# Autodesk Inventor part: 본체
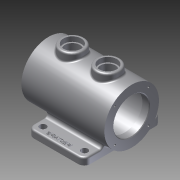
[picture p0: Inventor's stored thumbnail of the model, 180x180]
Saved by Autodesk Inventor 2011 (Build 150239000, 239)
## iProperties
Created: 2014-12
Part Number: 본체
Document SubType Name: Modeling
Designer: user
Density: 1 g/cm^3
Mass: 477.215 g
Surface Area: 1040.06 cm^2
Volume: 477.215 cm^3
Author: user
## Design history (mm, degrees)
sketch "스케치1"
  geometry: L1 (-47.5, 65)-(47.5, 65); L2 (47.5, 65)-(47.5, -65); L3 (47.5, -65)-(-47.5, -65); L4 (-47.5, -65)-(-47.5, 65); 3 further points
  constraints: 8 end point, 2 midpoint, 2 parallel, 1 horizontal, 1 horizontal alignment, 1 perpendicular, 1 vertical alignment
  dimensions: "d0" = 95 distance of L1.start L1.end; "d1" = 130 distance of L1.end L2.end
extrude "돌출1" new body sketch "스케치1" distance "d2" = 12; taper "d3" = 0 deg
sketch "스케치2"
  geometry: L1 (47.5, 12)-(47.5, 0) reference; L2 (47.5, 0)-(-47.5, 0) reference; L3 (-47.5, 0)-(-47.5, 12) reference; L4 (-47.5, 12)-(47.5, 12) reference; L5 (77.5, 50)-(-62.5, 50); L6 (77.5, 80)-(65.5, 80); L7 (65.5, 80)-(65.5, 87.5); L8 (65.5, 87.5)-(-50.5, 87.5); L9 (-50.5, 87.5)-(-50.5, 80); L10 (-50.5, 80)-(-62.5, 80); L11 (-62.5, 80)-(-62.5, 96); L12 (-62.5, 96)-(77.5, 96); L13 (77.5, 96)-(77.5, 80); 3 further points
  constraints: 18 end point, 7 parallel, 2 midpoint, 2 vertical alignment, 1 collinear, 1 perpendicular
  dimensions: "d4" = 50 distance between parallel lines of L2 L5; "d5" = 140 distance of L5.start L5.end; "d6" = 15 horizontal distance of L5.end L2.end; "d7" = 92 diameter of L12 L5; "d8" = 60 diameter of L6 L5; "d9" = 60 diameter of L10 L5; "d10" = 75 diameter of L8 L5; "d11" = 12 distance of L6.start L6.end; "d12" = 12 distance of L9.end L10.end
revolve "회전1" sketch "스케치2" stored, may be unused: angle "d13" = 90 deg
node "작업 평면1"
sketch "스케치3"
  geometry: L1 (62.5, 46)-(62.5, -46) reference; L2 (62.5, 46)-(-77.5, 46) reference; L3 (62.5, -46)-(-77.5, -46) reference; L4 (-77.5, 46)-(-77.5, -46) reference; C1 r 20 at (22.5, 0); C2 r 20 at (-37.5, 0); 2 further points
  constraints: 2 centre point, 2 horizontal alignment, 1 equal radius, 1 midpoint
  dimensions: "d15" = 40 distance from line of L1 C1.centre; "d16" = 40 distance from line of C2.centre L4; "d17" = 40 diameter of C1
extrude "돌출2" join sketch "스케치3" stored distance "d18" = 12; taper "d19" = 0 deg
hole "Hole1" diameter "d22" = 25; stored, may be unused: countersink angle "d26" = 90 deg, drill point angle "d28" = 118 deg; dims "d20" = 10, "d21" = 10, "d23" = 6, "d24" = 30, "d25" = 8, "d27" = 8
hole "Hole2" diameter "d31" = 25; stored, may be unused: countersink angle "d35" = 90 deg, drill point angle "d37" = 118 deg; dims "d29" = 10, "d30" = 10, "d32" = 6, "d33" = 30, "d34" = 8, "d36" = 8
sketch "스케치4" dims "d38" = 80
  geometry: L1 (0, 0)-(28.284, -28.284); L2 (0, 0)-(100.104, 0); C1 r 46 at (0, 0) reference; 1 further point
  constraints: 4 end point, 1 coincident, 1 horizontal, 3 other
  dimensions: "d39" = 45 deg angle of L1 L2
hole "Hole3" sketch "스케치4" at (28.284, -28.284) diameter "d40" = 3.242; stored, may be unused: countersink angle "d44" = 90 deg, drill point angle "d46" = 118 deg; dims "d41" = 8, "d42" = 4, "d43" = 2, "d45" = 10
sketch "스케치5" dims "d50" = 80
  geometry: L1 (0, 0)-(-28.284, 28.284); L2 (0, 0)-(-68.814, 0); C1 r 46 at (0, 0) reference; C2 r 30 at (0, 0) reference; 1 further point
  constraints: 4 end point, 2 coincident, 1 horizontal, 3 other
  dimensions: "d51" = 45 deg angle of L1 L2
hole "Hole4" sketch "스케치5" at (-28.284, 28.284) diameter "d52" = 3.242; stored, may be unused: countersink angle "d56" = 90 deg, drill point angle "d58" = 118 deg; dims "d53" = 8, "d54" = 4, "d55" = 2, "d57" = 10
fillet "모깎기1" dims "d62" = 5
fillet "모깎기2" dims "d63" = 3
chamfer "모따기1" distance "d64" = 1; stored, may be unused: second distance "d65" = 2, angle "d66" = 45 deg
chamfer "모따기2" distance "d67" = 1; stored, may be unused: second distance "d68" = 2, angle "d69" = 45 deg
fillet "모깎기3" dims "d70" = 10
fillet "모깎기4" dims "d71" = 3
fillet "모깎기5" dims "d72" = 3
fillet "모깎기6" dims "d73" = 3
fillet "모깎기7" dims "d74" = 3
sketch "스케치8"
  geometry: L1 (-23.239, -53.998)-(18.239, -53.998); L2 (18.239, -53.998)-(18.239, -60.002); L3 (18.239, -60.002)-(-23.239, -60.002); L4 (-23.239, -60.002)-(-23.239, -53.998); L5 (-23.239, -57)-(18.239, -57); L6 (-2.5, -60.002)-(-2.5, -53.998); L7 (-37.5, -65)-(37.5, -65) reference; C1 r 5.5 at (-37.5, -55) reference; 2 further points
  constraints: 5 midpoint, 4 end point, 2 other
  dimensions: "d89" = 8 distance from line of L7 point (-2.5, -57); "d90" = 35 horizontal distance of C1.centre point (-2.5, -57)
feature "엠보싱1" sketch "스케치8" dims "d0" = 95, "d1" = 130, "d91" = 1, "d92" = 0
sketch "스케치9"
  geometry: L1 (-8.07, -57.675)-(-6.136, -57.675) reference; L2 (-6.136, -57.675)-(-7.113, -55.104) reference; L3 (-7.113, -55.104)-(-8.07, -57.675) reference; L4 (-5.974, -58.089)-(-8.226, -58.089) reference; L5 (-8.226, -58.089)-(-8.796, -59.615) reference; L6 (-8.796, -59.615)-(-9.277, -59.615) reference; L7 (-9.277, -59.615)-(-7.378, -54.615) reference; L8 (-7.378, -54.615)-(-6.835, -54.615) reference; L9 (-6.835, -54.615)-(-4.936, -59.615) reference; L10 (-4.936, -59.615)-(-5.417, -59.615) reference; L11 (-5.417, -59.615)-(-5.974, -58.089) reference; L12 (-0.974, -55.029)-(-2.534, -55.029) reference; L13 (-2.534, -55.029)-(-2.534, -59.615) reference; L14 (-2.534, -59.615)-(-2.988, -59.615) reference; L15 (-2.988, -59.615)-(-2.988, -55.029) reference; L16 (-2.988, -55.029)-(-4.542, -55.029) reference; L17 (-4.542, -55.029)-(-4.542, -54.615) reference; L18 (-4.542, -54.615)-(-0.974, -54.615) reference; L19 (-0.974, -54.615)-(-0.974, -55.029) reference; L20 (3.938, -56.074)-(3.484, -56.074) reference; L21 (3.531, -57.98)-(3.979, -57.98) reference; L22 (-17.344, -59.439)-(-17.344, -59.819) reference; L23 (-17.344, -59.819)-(-21.693, -59.819) reference; L24 (-21.693, -59.819)-(-21.693, -58.191) reference; L25 (-21.693, -58.191)-(-21.34, -58.191) reference; L26 (-21.231, -58.408)-(-21.231, -59.439) reference; L27 (-21.231, -59.439)-(-17.344, -59.439) reference; L28 (7.914, -57.248)-(7.609, -57.594) reference; L29 (4.915, -57.797)-(4.603, -57.458) reference; L30 (6.17, -54.344)-(6.571, -54.344) reference; L31 (-16.442, -56.746)-(-17.561, -56.746) reference; L32 (-17.561, -56.746)-(-17.561, -58.489) reference; L33 (-17.561, -58.489)-(-18.036, -58.489) reference; L34 (-18.036, -58.489)-(-18.036, -53.998) reference; L35 (-18.036, -53.998)-(-17.731, -53.998) reference; L36 (-17.561, -54.263)-(-17.561, -56.352) reference; L37 (-17.561, -56.352)-(-16.442, -56.352) reference; L38 (-16.442, -56.352)-(-16.442, -56.746) reference; L39 (6.218, -59.629)-(10.092, -59.629) reference; L40 (10.092, -59.629)-(10.092, -60.002) reference; L41 (10.092, -60.002)-(5.77, -60.002) reference; L42 (5.77, -60.002)-(5.77, -58.089) reference; L43 (5.77, -58.089)-(6.102, -58.089) reference; L44 (6.218, -58.292)-(6.218, -59.629) reference; L45 (8.789, -54.391)-(8.789, -58.415) reference; L46 (8.789, -58.415)-(8.334, -58.415) reference; L47 (8.334, -58.415)-(8.334, -55.993) reference; L48 (8.334, -55.993)-(7.303, -55.993) reference; L49 (7.303, -55.993)-(7.303, -55.647) reference; L50 (7.303, -55.647)-(8.334, -55.647) reference; L51 (8.334, -55.647)-(8.334, -54.154) reference; L52 (8.334, -54.154)-(8.708, -54.154) reference; L53 (-22.547, -55.382)-(-22.547, -55.029) reference; L54 (-22.547, -55.029)-(-18.782, -55.029) reference; L55 (-18.782, -55.029)-(-18.782, -55.382) reference; L56 (-18.782, -55.382)-(-22.547, -55.382) reference; L57 (9.949, -54.29)-(9.949, -58.666) reference; L58 (9.949, -58.666)-(9.495, -58.666) reference; L59 (9.495, -58.666)-(9.495, -54.079) reference; L60 (9.495, -54.079)-(9.854, -54.079) reference; L61 (-21.353, -54.575)-(-21.353, -54.222) reference; L62 (-21.353, -54.222)-(-19.874, -54.222) reference; L63 (-19.874, -54.222)-(-19.874, -54.575) reference; L64 (-19.874, -54.575)-(-21.353, -54.575) reference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; A1 r 7 centre (37.5, -55) between (37.5, -62) and (44.5, -55) reference; A2 r 7 centre (-37.5, -55) between (-44.5, -55) and (-37.5, -62) reference; A3 r 7 centre (37.5, 55) between (44.5, 55) and (37.5, 62) reference; A4 r 7 centre (-37.5, 55) between (-37.5, 62) and (-44.5, 55) reference; 64 further points
  constraints: 1 vertical alignment, 84 other
  dimensions: "d93" = 104 distance of point (35, -52) point (35, 52); "d94" = 82.5 distance from line of L119 point (35, 52); "d95" = 13 distance from line of L120 point (35, 52); "d96" = 13 distance from line of L121 point (35, -52) (derived)
hole "Hole7" sketch "스케치9" at (35, 52), (35, -52) diameter "d97" = 11; stored, may be unused: countersink angle "d101" = 90 deg, drill point angle "d103" = 118 deg; dims "d98" = 6, "d99" = 4, "d100" = 2, "d102" = 8
node "솔리드1"
pattern_circular "원형 패턴1" dims angle "d48" = 360 deg
pattern_circular "원형 패턴2" dims angle "d60" = 360 deg
mirror "대칭1"
node "작업 평면2"
node "절단 모서리 투영1"
node "절단 모서리 투영2"
other parameters: "d14" = 106
